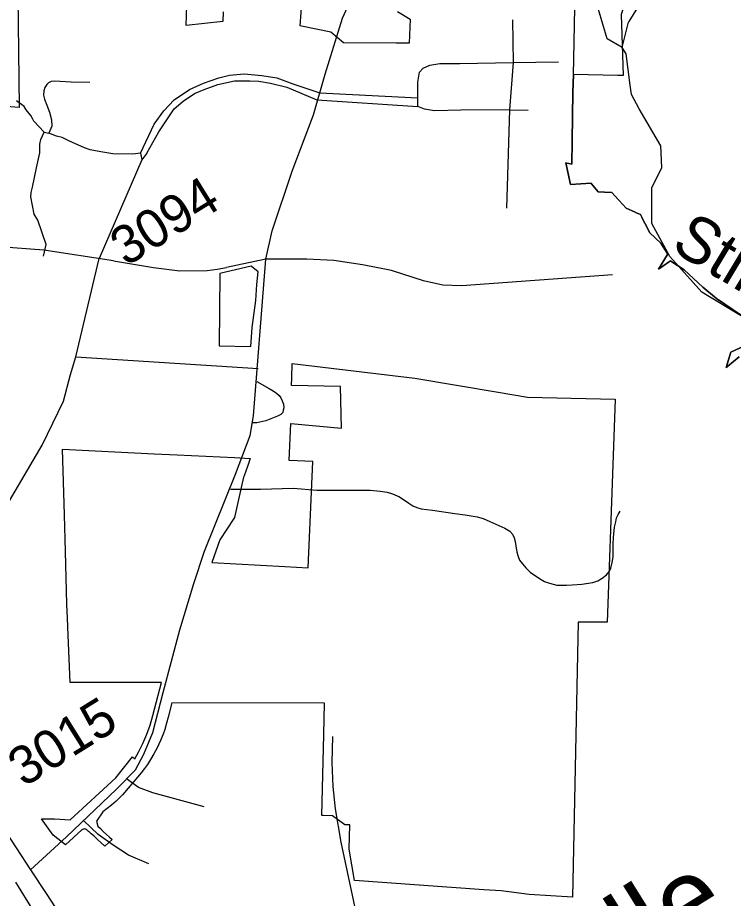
# Model space of a CAD drawing. Extents: x 2001466 to 31450019, y -30647475 to 847247.
# Drawn here: x 31436559 to 31441239, y -30630698 to -30624939 of the extents above; entities that cross this region are included whole.
import ezdxf

# ---------------------------------------------------------------- set-up
doc = ezdxf.new("R2010")
doc.units = 0
for name, color, linetype in [('Exist Boundary Political City Limit New', 7, 'Continuous'), ('Exist Boundary Political City Limit New Hole', 7, 'Continuous'), ('Exist Civil Demographics City Label', 7, 'Continuous'), ('Exist Hydrographic Creek Single Shore', 7, 'Continuous'), ('Exist Hydrographic Creek Single Shore Label', 7, 'Continuous'), ('Exist Railroad Mainline', 7, 'Continuous'), ('Exist Road Non-System Type 51', 7, 'Continuous'), ('Exist Road Primary NC Attributed', 7, 'Continuous'), ('Exist Road Secondary Type 41 Attributed', 7, 'Continuous'), ('Exist Road Secondary Type 51 Attributed', 7, 'Continuous'), ('Exist Road Secondary Type 51 Number Label', 7, 'Continuous'), ('Map Preparation Boundary City Limit Buffer Line', 7, 'Continuous')]:
    doc.layers.add(name, color=color, linetype=linetype)

msp = doc.modelspace()

# ---------------------------------------------------------------- linework, layer by layer
at = {"layer": 'Exist Boundary Political City Limit New'}
for points in [[(31440664.3, -30624584.6), (31440622.6, -30624648.1), (31440564.8, -30624737), (31440504.1, -30624919.1), (31440518.3, -30625317.9), (31440493, -30625317.1), (31440483.9, -30625317), (31440193.6, -30625312.4)], [(31440193.6, -30625312.4), (31440189, -30625426.9), (31440184.3, -30625744.6), (31440182, -30625898.1), (31440143.8, -30625888.2), (31440173, -30626031.2), (31440308.6, -30626022.3), (31440311.5, -30626025.8), (31440354.3, -30626079.3), (31440395.6, -30626081.3), (31440444.1, -30626083.5), (31440488.3, -30626131.7), (31440488.8, -30626132.2), (31440537.9, -30626186.1), (31440596.6, -30626212.4), (31440597.8, -30626213), (31440631, -30626227.8), (31440639, -30626243.5), (31440639.4, -30626244.2), (31440658.4, -30626281.3), (31440659.8, -30626284.1), (31440691.6, -30626346.2), (31440763.4, -30626414.4), (31440809.5, -30626487), (31440808.5, -30626488.5), (31440808.3, -30626489.1), (31440748.9, -30626584.8), (31440827.8, -30626530.1), (31440829.3, -30626531), (31440917.8, -30626588), (31441038.5, -30626701.9), (31441128.9, -30626776.1), (31441408, -30626965.1)], [(31441427.9, -30627030.1), (31441221.4, -30627126.1), (31441192.3, -30627226.5), (31441200.8, -30627219.7), (31441201.4, -30627219.1), (31441276.3, -30627158.4)]]:
    msp.add_lwpolyline(points, dxfattribs=at)
at = {"layer": 'Exist Boundary Political City Limit New Hole'}
for points in [[(31438131.3, -30626601), (31438084.8, -30626563.8), (31437881.8, -30626611.5), (31437875.6, -30627084.4), (31438083.6, -30627090.6), (31438091.6, -30626966.3), (31438116, -30626789.5), (31438123.5, -30626683.9), (31438131.3, -30626601)], [(31438726.1, -30630377.6), (31438729.9, -30630218.3), (31438697.9, -30630217.3), (31438616.6, -30630157.9), (31438556.3, -30630157), (31438546.9, -30630156.8), (31438560, -30629627.4), (31438565, -30629423), (31437567.3, -30629420.3), (31437543.6, -30629513.6), (31437533.1, -30629553.6), (31437520.5, -30629593.8), (31437509.6, -30629624.4), (31437492.1, -30629667.1), (31437470.4, -30629714), (31437450.1, -30629752.4), (31437427.9, -30629790.1), (31437407.1, -30629822), (31437387.5, -30629850.1), (31437366.6, -30629877.5), (31437257.5, -30630005.4), (31437244.4, -30630021.8), (31437227.6, -30630038.6), (31437203.6, -30630062.4), (31437172.8, -30630089.9), (31437116.5, -30630132.8), (31437074, -30630193.4), (31437083.8, -30630225.5), (31437099.8, -30630242.5), (31437118.6, -30630261.6), (31437139.1, -30630280.9), (31437159.4, -30630298.6), (31437176.5, -30630312.6), (31437129.1, -30630355.9), (31437103.1, -30630332.5), (31437084.1, -30630316.5), (31437071.9, -30630304.6), (31437064.9, -30630298.5), (31437056.4, -30630290.1), (31437047.3, -30630282.6), (31437039.5, -30630275.7), (31437033.1, -30630270), (31437029.3, -30630266.4), (31437022, -30630260), (31437015.4, -30630254.1), (31437009.8, -30630248.9), (31437007.1, -30630247.4), (31437003.6, -30630245.9), (31437001.4, -30630245.3), (31436996.4, -30630244.6), (31436991.8, -30630245), (31436989.4, -30630245.5), (31436985.3, -30630247), (31436982.4, -30630248.7), (31436979.3, -30630250.9), (31436871.8, -30630348), (31436790.8, -30630284.3), (31436714.4, -30630177.6), (31436768.3, -30630178), (31436800, -30630178), (31436902.6, -30630185.5), (31437201.1, -30629910.1), (31437310.1, -30629773.5), (31437325.3, -30629785.4), (31437352.1, -30629737.6), (31437377.9, -30629686.3), (31437404.1, -30629624.8), (31437425.3, -30629565.3), (31437443.4, -30629502.4), (31437498.3, -30629286.5), (31436901.6, -30629286.5), (31436888.8, -30628976.4), (31436884.1, -30628865.2), (31436881.5, -30628775.5), (31436871.3, -30628429.3), (31436864.1, -30628190.9), (31436859.9, -30628046.1), (31436851.5, -30627761.3), (31437452.1, -30627791), (31437601.3, -30627799.1), (31437975.6, -30627816), (31438079.6, -30627821.8), (31438061.5, -30627875.5), (31438039.4, -30627934.6), (31438036, -30627943.3), (31438020.8, -30628010.9), (31437976.5, -30628207.3), (31437972.4, -30628213.6), (31437881.3, -30628354.6), (31437829, -30628501.3), (31438305.3, -30628528.3), (31438459, -30628537.1), (31438488.9, -30627841.8), (31438335, -30627834.3), (31438344.3, -30627592.9), (31438676.6, -30627623), (31438669.6, -30627350.5), (31438349.9, -30627345), (31438351.3, -30627294), (31438353.8, -30627202)], [(31438353.8, -30627202), (31439155.1, -30627297.4), (31439701.5, -30627388.7), (31439892, -30627420.4), (31440466.3, -30627433.5), (31440451, -30627862.5), (31440413.6, -30628892.2), (31440222.8, -30628891.8), (31440187.6, -30630690.4), (31439903.1, -30630672.4), (31439721, -30630649.4), (31439606.4, -30630641.5), (31438762.1, -30630582.3), (31438726.1, -30630377.6)]]:
    msp.add_lwpolyline(points, dxfattribs=at)
at = {"layer": 'Exist Hydrographic Creek Single Shore'}
for points in [[(31440512.4, -30625135.9), (31440412.4, -30625078), (31440328.5, -30624787.5), (31440294.5, -30624770.5), (31440277.4, -30624694.7), (31440194.4, -30624627.4), (31439927.4, -30624579.3), (31439877.4, -30624443.7), (31439760.5, -30624369.1), (31439693.5, -30624262.8), (31439260.4, -30624053.8), (31438998.6, -30623756.5), (31438963.5, -30623729.3), (31438939.7, -30623703.8), (31438905.2, -30623679.5), (31438856.5, -30623647.7), (31438567.5, -30623465.4), (31438475.4, -30623365.1)], [(31440556.4, -30624964.6), (31440852.4, -30624486.6), (31440907.2, -30624351.4)], [(31440512.4, -30625135.9), (31440553.4, -30624969.4), (31440556.4, -30624964.6)], [(31440563.6, -30625380.7), (31440537.4, -30625175.8), (31440512.4, -30625135.9)], [(31440975.8, -30626672.3), (31440822.5, -30626500.6), (31440705.4, -30626284.9), (31440705.4, -30626051.9), (31440771.4, -30625918.8), (31440763.4, -30625777.5), (31440621.5, -30625535.1), (31440571.5, -30625442.2), (31440563.6, -30625380.7)], [(31441072.1, -30626758.9), (31441031.4, -30626734.5), (31440975.8, -30626672.3)], [(31441459.5, -30627015.2), (31441432.5, -30626975.7), (31441072.1, -30626758.9)]]:
    msp.add_lwpolyline(points, dxfattribs=at)
at = {"layer": 'Exist Railroad Mainline'}
msp.add_lwpolyline([(31436544.7, -30630592.9), (31436660.9, -30630779.3), (31436781, -30630969.7), (31436852.4, -30631095.2), (31436927.4, -30631244.7), (31436963.4, -30631341.5), (31437012.7, -30631474.5), (31437064.8, -30631647.8), (31437072.6, -30631673.7), (31437118.8, -30631858.7), (31437152.7, -30632059.4), (31437182.5, -30632264), (31437219.7, -30632598.8), (31437255, -30632927.5), (31437282.1, -30633166.1), (31437290.7, -30633227.3), (31437301.3, -30633302.5), (31437322, -30633464.9), (31437344.3, -30633643.4), (31437384, -30633854.2), (31437407.8, -30633962.7), (31437428.1, -30634047.1)], dxfattribs=at)
at = {"layer": 'Exist Road Non-System Type 51'}
for p, q in [((31439794.2, -30624953.4), (31439798.1, -30625232.8)), ((31439798.1, -30625232.8), (31439774.6, -30625541.7)), ((31439798.1, -30625232.8), (31440096.1, -30625229.2)), ((31438533.8, -30625432.2), (31439174.8, -30625464.5)), ((31438514.2, -30625476.1), (31439174.8, -30625519.6)), ((31439174.8, -30625519.6), (31439174.8, -30625464.5)), ((31439774.6, -30625541.7), (31439755, -30626185.1)), ((31439774.6, -30625541.7), (31439896.2, -30625545.4)), ((31436731.9, -30625689.1), (31436763.4, -30625694.3)), ((31437363, -30625825), (31437311.5, -30625831.6))]:
    msp.add_line(p, q, dxfattribs=at)
for points in [[(31439174.8, -30625464.5), (31439174.8, -30625361.5), (31439186.5, -30625295.3), (31439210.1, -30625269.6), (31439253.2, -30625251.2), (31439319.8, -30625240.2), (31439449.2, -30625240.2), (31439798.1, -30625232.8)], [(31437363, -30625825), (31437451.8, -30625636.5), (31437514.8, -30625549.7), (31437583.2, -30625476.1), (31437683, -30625410.4), (31437775, -30625368.3), (31437874.8, -30625334.1), (31437943.1, -30625315.7), (31438040.3, -30625307.8), (31438155.9, -30625318.3), (31438253.1, -30625334.1), (31438357.1, -30625371.6), (31438533.8, -30625432.2)], [(31437031.7, -30625362.6), (31436907.7, -30625362.1), (31436835.8, -30625356.6), (31436801.9, -30625353.9), (31436777.8, -30625357.4), (31436761.6, -30625365.1), (31436749.4, -30625376.8), (31436737, -30625396.6), (31436730.6, -30625418.5), (31436728, -30625446.4), (31436733.4, -30625472.5), (31436750.3, -30625512.9), (31436766, -30625557.6), (31436779.2, -30625607.5), (31436781.8, -30625649.6), (31436763.4, -30625694.3)], [(31437404.5, -30625826.6), (31437482, -30625687.1), (31437583.2, -30625536.6), (31437641, -30625486.6), (31437714.5, -30625436.6), (31437777.6, -30625410.4), (31437866.9, -30625376.2), (31437977.3, -30625352.5), (31438077.1, -30625352.5), (31438134.9, -30625355.1), (31438211.1, -30625368.3), (31438318.8, -30625394.6), (31438514.2, -30625476.1)], [(31436731.9, -30625689.1), (31436663.6, -30625615.4), (31436655.7, -30625599.7), (31436645.2, -30625578.6), (31436613.7, -30625541.8), (31436600.5, -30625520.8), (31436551.2, -30625482.8)], [(31439774.6, -30625541.7), (31439457.1, -30625545.4), (31439284.6, -30625549), (31439217.9, -30625538), (31439174.8, -30625519.6)], [(31436728.3, -30626499.7), (31436745.1, -30626422.5), (31436691.4, -30626264.7), (31436667.9, -30626224.4), (31436644.4, -30626110.7), (31436647, -30626082.8), (31436655.7, -30626047), (31436681.3, -30625922.3), (31436704.3, -30625823.9), (31436703, -30625767.9), (31436710.9, -30625736.4), (31436731.9, -30625689.1)], [(31437311.5, -30625831.6), (31437180.2, -30625829.7), (31437102.4, -30625816.1), (31437032.7, -30625804.7), (31436996.9, -30625791.9), (31436893.9, -30625745.8), (31436850.1, -30625723.2), (31436813.3, -30625715.3), (31436763.4, -30625694.3)], [(31437363, -30625825), (31437371.3, -30625869.8)], [(31437404.5, -30625826.6), (31437371.3, -30625869.8)], [(31437371.3, -30625869.8), (31437092, -30626515.1)], [(31435560.7, -30628832.1), (31435841.3, -30628646.6), (31435981.6, -30628581.4), (31436141.9, -30628506.2), (31436267.1, -30628426), (31436352.3, -30628335.7), (31436447.5, -30628200.3), (31436718.1, -30627734.1), (31436858.3, -30627448.3), (31436903.4, -30627272.8), (31436938.5, -30627157.5), (31437092, -30626515.1)], [(31437186, -30626529.7), (31437447.7, -30626573), (31437618.8, -30626594.6), (31437797.5, -30626593), (31437863.2, -30626585.2), (31437923.8, -30626573.5)], [(31440449.2, -30626620.6), (31439464.1, -30626693.9), (31439337.9, -30626689.8), (31439211.7, -30626661.3), (31439004.1, -30626592), (31438812.8, -30626555.4), (31438625.6, -30626526.9), (31438450.5, -30626518.7), (31438182, -30626518.5)], [(31436938.5, -30627157.5), (31438130.9, -30627232.7)], [(31438122.3, -30627319.2), (31438202.4, -30627363.5), (31438228.6, -30627379), (31438252.2, -30627395.8), (31438268.3, -30627409.9), (31438279.7, -30627424.7), (31438289.1, -30627444.9), (31438297.2, -30627466.4), (31438298.6, -30627491.3), (31438295.9, -30627505.5), (31438293.2, -30627522.3), (31438280.4, -30627535.1), (31438258.9, -30627545.8), (31438225.3, -30627558), (31438182.2, -30627574.8), (31438121.7, -30627588.9), (31438104.2, -30627588.9), (31438092.7, -30627588.4)], [(31437949.7, -30628022.3), (31438146.5, -30628022.3), (31438360.4, -30628016.9), (31438514.4, -30628028.2), (31438631.5, -30628028.2), (31438863.2, -30628030.2), (31438929.1, -30628035.5), (31438975, -30628042.5), (31439010.7, -30628053.2), (31439054.4, -30628072.1), (31439117.5, -30628113.4), (31439143.1, -30628131.9), (31439168.9, -30628142.4), (31439196.7, -30628151), (31439270.6, -30628160.5), (31439418.1, -30628181.5), (31439483.9, -30628190.9), (31439563.7, -30628204.5), (31439603.4, -30628215.3), (31439647.1, -30628234.2), (31439744.2, -30628278.2), (31439775.8, -30628296.8), (31439795.4, -30628317.2), (31439804.9, -30628341.4), (31439812.4, -30628365.6), (31439815.8, -30628393.7), (31439823, -30628433.8), (31439830.4, -30628462), (31439839.9, -30628486.2), (31439859.4, -30628510.6), (31439880.9, -30628537), (31439910.3, -30628565.6), (31439971.5, -30628606.9), (31440003.1, -30628625.5), (31440036.8, -30628638.2), (31440084.6, -30628651.2), (31440146.6, -30628650.4), (31440184, -30628648.3)], [(31440184, -30628648.3), (31440248.7, -30628644.5), (31440318.9, -30628634), (31440353.1, -30628622.7), (31440381.5, -30628605.2), (31440410, -30628581.8), (31440428.5, -30628558.2), (31440436.9, -30628538.4), (31440445.6, -30628502.6), (31440452.4, -30628464.7), (31440452.1, -30628382.7), (31440455, -30628338.7), (31440460.3, -30628270.8), (31440469, -30628237), (31440473.6, -30628211.1), (31440486.1, -30628187.4), (31440498.5, -30628165.6)], [(31438777.5, -30631793.9), (31438730.8, -30631628.4), (31438721.9, -30631468.3), (31438735.3, -30631317), (31438757.5, -30631192.4), (31438790, -30631008.7), (31438790, -30630914.3), (31438778.2, -30630822.8), (31438757.6, -30630719.6), (31438675, -30630330.1), (31438636.7, -30630111.8), (31438622, -30629967.2), (31438616.1, -30629810.9), (31438619, -30629639.8)], [(31437778.8, -30630100), (31437442.6, -30630008.5), (31437348.3, -30629973.1), (31437270.7, -30629916.9)], [(31437416.1, -30630471.8), (31437283.4, -30630415.7), (31437183.2, -30630350.8), (31437085.9, -30630280), (31436989.8, -30630188.8)]]:
    msp.add_lwpolyline(points, dxfattribs=at)
at = {"layer": 'Exist Road Primary NC Attributed'}
for points in [[(31435238.4, -30628273.1), (31435410.6, -30628525.9), (31435643.9, -30628916.4), (31435877.2, -30629285.2), (31436017.2, -30629509), (31436265, -30629901.1), (31436454.9, -30630223.2), (31436642.4, -30630511.4)], [(31436642.4, -30630511.4), (31436745.4, -30630667.2), (31436899.8, -30630904.4), (31437049.5, -30631142.7), (31437167, -30631326.3), (31437245.8, -30631480.1), (31437318.2, -30631678.1), (31437424.4, -30632012.3), (31437543.5, -30632362.5), (31437701.2, -30632840.8), (31437801, -30633096.8), (31437947.4, -30633559.8), (31438018.2, -30633769.1), (31438045.6, -30633891.5), (31438071.3, -30634084)]]:
    msp.add_lwpolyline(points, dxfattribs=at)
at = {"layer": 'Exist Road Secondary Type 41 Attributed'}
for points in [[(31437186, -30626529.7), (31436730.4, -30626458.9), (31436148.6, -30626415.4), (31435707.6, -30626391.2), (31435281.9, -30626360.6), (31435161.2, -30626347.8), (31435080.7, -30626301.1), (31435016.4, -30626259.2), (31434932.7, -30626173.8), (31434869.9, -30626109.4), (31434802.3, -30626064.3), (31434728.3, -30626036.9), (31434647.8, -30626020.8), (31434442.6, -30626016), (31434016.1, -30626014.4), (31433819.1, -30626017.8)], [(31438182, -30626518.5), (31437923.8, -30626573.5)]]:
    msp.add_lwpolyline(points, dxfattribs=at)
at = {"layer": 'Exist Road Secondary Type 51 Attributed'}
for points in [[(31438182, -30626518.5), (31438223.9, -30626333.3), (31438354.2, -30625943.5), (31438492.9, -30625575.8), (31438568.6, -30625310.1), (31438682.5, -30624943.4), (31438737.3, -30624821), (31438870.8, -30624611.7), (31438951.3, -30624488.5)], [(31436642.4, -30630511.4), (31436878.4, -30630295.1), (31437205.1, -30629983.4), (31437329, -30629857.8), (31437383.8, -30629754.7), (31437443.3, -30629613.8), (31437510.9, -30629352.9), (31437618.7, -30628943.1), (31437710.5, -30628640.3), (31437781.3, -30628427.7), (31437984.1, -30627924.4), (31438079, -30627672.4), (31438099.9, -30627543.6), (31438182, -30626518.5)]]:
    msp.add_lwpolyline(points, dxfattribs=at)
at = {"layer": 'Map Preparation Boundary City Limit Buffer Line'}
for points in [[(31440193.6, -30625312.4), (31440195.8, -30625208.1), (31440207.3, -30624650.4), (31440183.4, -30624603.1), (31440201.1, -30624527), (31440201.1, -30624516.7), (31440258.8, -30624371.8), (31440252.5, -30624178.8), (31440398.1, -30624135.5), (31440556, -30624213.5), (31440452.1, -30624388.1), (31440581.5, -30624475.5), (31440664.3, -30624584.6)], [(31436554.1, -30624273.6), (31436564.1, -30625159.1), (31436568.3, -30625527.3), (31436155, -30625494.6)], [(31440664.3, -30624584.6), (31440622.6, -30624648.1), (31440564.8, -30624737), (31440504.1, -30624919.1), (31440518.3, -30625317.9), (31440493, -30625317.1), (31440483.9, -30625317), (31440193.6, -30625312.4)], [(31437901.5, -30624902.1), (31437899.5, -30624964.8), (31437661.3, -30624992), (31437665.1, -30624860)], [(31439041.8, -30624900.4), (31439124.5, -30624950.3), (31439118.4, -30625106.2), (31439033.6, -30625106), (31438690.1, -30625104.9), (31438607.6, -30625033.8), (31438414.6, -30624995.6), (31438406.3, -30624994), (31438420, -30624817.3)], [(31441408, -30626965.1), (31441128.9, -30626776.1), (31441038.5, -30626701.9), (31440917.8, -30626588), (31440829.3, -30626531), (31440827.8, -30626530.1), (31440748.9, -30626584.8), (31440808.3, -30626489.1), (31440808.5, -30626488.5), (31440809.5, -30626487), (31440763.4, -30626414.4), (31440691.6, -30626346.2), (31440659.8, -30626284.1), (31440658.4, -30626281.3), (31440639.4, -30626244.2), (31440639, -30626243.5), (31440631, -30626227.8), (31440597.8, -30626213), (31440596.6, -30626212.4), (31440537.9, -30626186.1), (31440488.8, -30626132.2), (31440488.3, -30626131.7), (31440444.1, -30626083.5), (31440395.6, -30626081.3), (31440354.3, -30626079.3), (31440311.5, -30626025.8), (31440308.6, -30626022.3), (31440173, -30626031.2), (31440143.8, -30625888.2), (31440182, -30625898.1), (31440184.3, -30625744.6), (31440189, -30625426.9), (31440193.6, -30625312.4)], [(31440193.6, -30625312.4), (31440189, -30625426.9), (31440184.3, -30625744.6), (31440182, -30625898.1), (31440143.8, -30625888.2), (31440173, -30626031.2), (31440308.6, -30626022.3), (31440311.5, -30626025.8), (31440354.3, -30626079.3), (31440395.6, -30626081.3), (31440444.1, -30626083.5), (31440488.3, -30626131.7), (31440488.8, -30626132.2), (31440537.9, -30626186.1), (31440596.6, -30626212.4), (31440597.8, -30626213), (31440631, -30626227.8), (31440639, -30626243.5), (31440639.4, -30626244.2), (31440658.4, -30626281.3), (31440659.8, -30626284.1), (31440691.6, -30626346.2), (31440763.4, -30626414.4), (31440809.5, -30626487), (31440808.5, -30626488.5), (31440808.3, -30626489.1), (31440748.9, -30626584.8), (31440827.8, -30626530.1), (31440829.3, -30626531), (31440917.8, -30626588), (31441038.5, -30626701.9), (31441128.9, -30626776.1), (31441408, -30626965.1)], [(31438131.3, -30626601), (31438084.8, -30626563.8), (31437881.8, -30626611.5), (31437875.6, -30627084.4), (31438083.6, -30627090.6), (31438091.6, -30626966.3), (31438116, -30626789.5), (31438123.5, -30626683.9), (31438131.3, -30626601)], [(31441276.3, -30627158.4), (31441201.4, -30627219.1), (31441200.8, -30627219.7), (31441192.3, -30627226.5), (31441221.4, -30627126.1), (31441427.9, -30627030.1)], [(31441427.9, -30627030.1), (31441221.4, -30627126.1), (31441192.3, -30627226.5), (31441200.8, -30627219.7), (31441201.4, -30627219.1), (31441276.3, -30627158.4)], [(31438726.1, -30630377.6), (31438729.9, -30630218.3), (31438697.9, -30630217.3), (31438616.6, -30630157.9), (31438556.3, -30630157), (31438546.9, -30630156.8), (31438560, -30629627.4), (31438565, -30629423), (31437567.3, -30629420.3), (31437543.6, -30629513.6), (31437533.1, -30629553.6), (31437520.5, -30629593.8), (31437509.6, -30629624.4), (31437492.1, -30629667.1), (31437470.4, -30629714), (31437450.1, -30629752.4), (31437427.9, -30629790.1), (31437407.1, -30629822), (31437387.5, -30629850.1), (31437366.6, -30629877.5), (31437257.5, -30630005.4), (31437244.4, -30630021.8), (31437227.6, -30630038.6), (31437203.6, -30630062.4), (31437172.8, -30630089.9), (31437116.5, -30630132.8), (31437074, -30630193.4), (31437083.8, -30630225.5), (31437099.8, -30630242.5), (31437118.6, -30630261.6), (31437139.1, -30630280.9), (31437159.4, -30630298.6), (31437176.5, -30630312.6), (31437129.1, -30630355.9), (31437103.1, -30630332.5), (31437084.1, -30630316.5), (31437071.9, -30630304.6), (31437064.9, -30630298.5), (31437056.4, -30630290.1), (31437047.3, -30630282.6), (31437039.5, -30630275.7), (31437033.1, -30630270), (31437029.3, -30630266.4), (31437022, -30630260), (31437015.4, -30630254.1), (31437009.8, -30630248.9), (31437007.1, -30630247.4), (31437003.6, -30630245.9), (31437001.4, -30630245.3), (31436996.4, -30630244.6), (31436991.8, -30630245), (31436989.4, -30630245.5), (31436985.3, -30630247), (31436982.4, -30630248.7), (31436979.3, -30630250.9), (31436871.8, -30630348), (31436790.8, -30630284.3), (31436714.4, -30630177.6), (31436768.3, -30630178), (31436800, -30630178), (31436902.6, -30630185.5), (31437201.1, -30629910.1), (31437310.1, -30629773.5), (31437325.3, -30629785.4), (31437352.1, -30629737.6), (31437377.9, -30629686.3), (31437404.1, -30629624.8), (31437425.3, -30629565.3), (31437443.4, -30629502.4), (31437498.3, -30629286.5), (31436901.6, -30629286.5), (31436888.8, -30628976.4), (31436884.1, -30628865.2), (31436881.5, -30628775.5), (31436871.3, -30628429.3), (31436864.1, -30628190.9), (31436859.9, -30628046.1), (31436851.5, -30627761.3), (31437452.1, -30627791), (31437601.3, -30627799.1), (31437975.6, -30627816), (31438079.6, -30627821.8), (31438061.5, -30627875.5), (31438039.4, -30627934.6), (31438036, -30627943.3), (31438020.8, -30628010.9), (31437976.5, -30628207.3), (31437972.4, -30628213.6), (31437881.3, -30628354.6), (31437829, -30628501.3), (31438305.3, -30628528.3), (31438459, -30628537.1), (31438488.9, -30627841.8), (31438335, -30627834.3), (31438344.3, -30627592.9), (31438676.6, -30627623), (31438669.6, -30627350.5), (31438349.9, -30627345), (31438351.3, -30627294), (31438353.8, -30627202)], [(31438353.8, -30627202), (31439155.1, -30627297.4), (31439701.5, -30627388.7), (31439892, -30627420.4), (31440466.3, -30627433.5), (31440451, -30627862.5), (31440413.6, -30628892.2), (31440222.8, -30628891.8), (31440187.6, -30630690.4), (31439903.1, -30630672.4), (31439721, -30630649.4), (31439606.4, -30630641.5), (31438762.1, -30630582.3), (31438726.1, -30630377.6)]]:
    msp.add_lwpolyline(points, dxfattribs=at)

# ---------------------------------------------------------------- texts
at = {"layer": 'Exist Civil Demographics City Label'}
msp.add_text('Morrisville', height=530, rotation=31.91803, dxfattribs=at).set_placement((31438533.4, -30632509.8))
at = {"layer": 'Exist Hydrographic Creek Single Shore Label'}
msp.add_text('Stirrup', height=300, rotation=328.97907, dxfattribs=at).set_placement((31440821, -30626454.7))
at = {"layer": 'Exist Road Secondary Type 51 Number Label'}
for s, p in [('3094', (31437267.6, -30626570.4)), ('3015', (31436599, -30629974.5))]:
    msp.add_text(s, height=250, rotation=31.91803, dxfattribs=at).set_placement(p)

doc.saveas('drawing.dxf')
